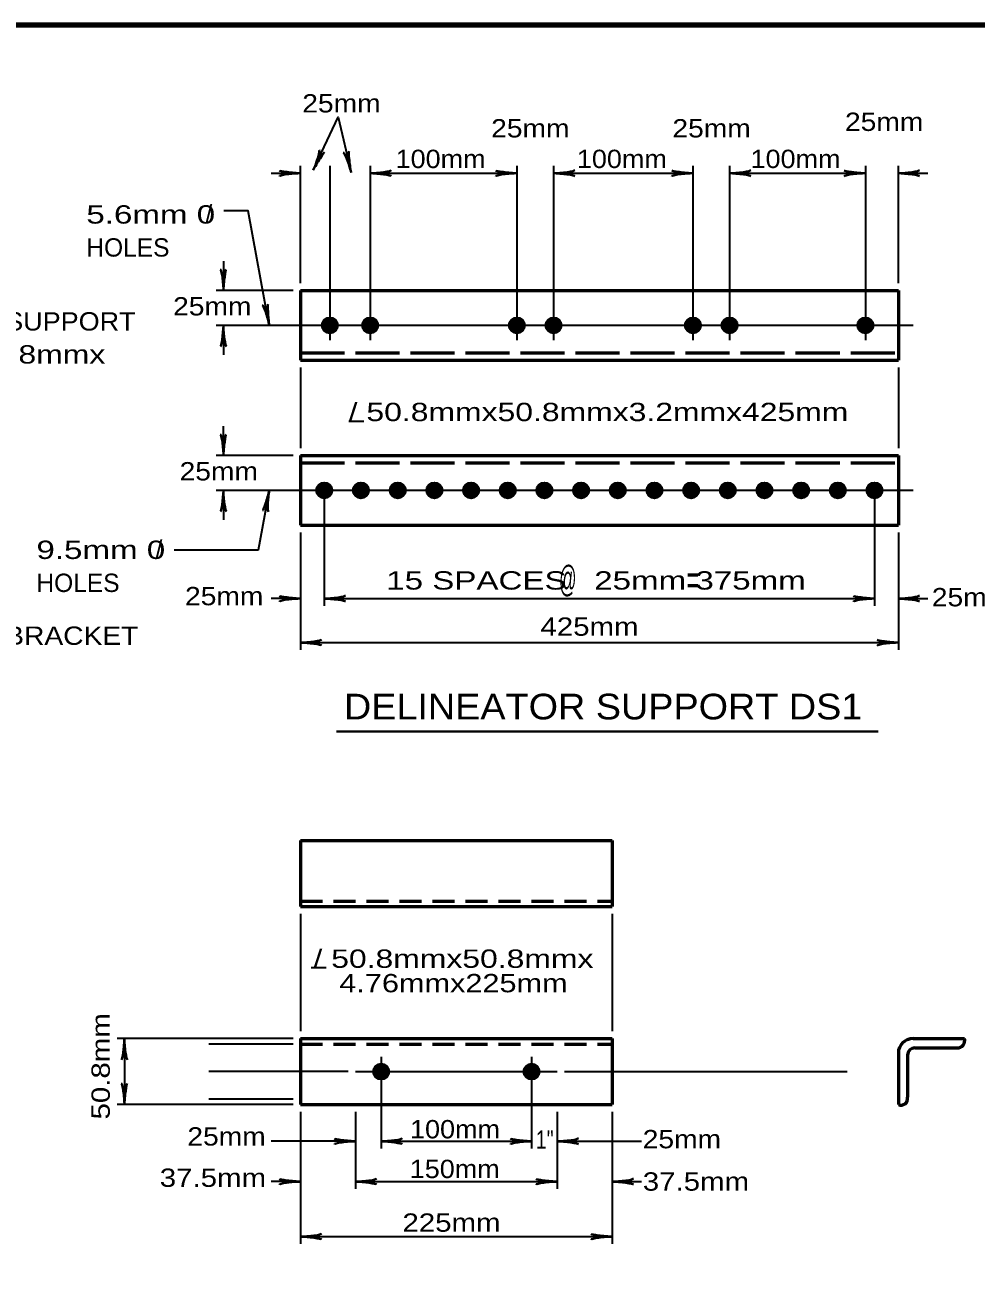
# Model space of a CAD drawing. Extents: x -105 to 751, y -65 to 479.
# Drawn here: x 441.4 to 597, y 268.5 to 472.7 of the extents above; entities that cross this region are included whole.
import ezdxf
from ezdxf.enums import TextEntityAlignment as Align

# ---------------------------------------------------------------- set-up
doc = ezdxf.new("R2010")
doc.units = 0
doc.header["$LTSCALE"] = 1.2
doc.linetypes.add('LONG_DASHED', pattern=[7.5, 6, -1.5])
doc.linetypes.add('MEDIUM_DASHED', pattern=[4.5, 3, -1.5])
doc.layers.add('1', color=7, linetype='Continuous', lineweight=35)

msp = doc.modelspace()

# ---------------------------------------------------------------- hatches: boundary and pattern name
at = {"layer": '1'}
for points in [[(492.465, 423.538, 1), (490.065, 423.538, 1)], [(499.065, 423.538, 1), (496.665, 423.538, 1)], [(523.065, 423.538, 1), (520.665, 423.538, 1)], [(529.065, 423.538, 1), (526.665, 423.538, 1)], [(551.865, 423.538, 1), (549.465, 423.538, 1)], [(557.865, 423.538, 1), (555.465, 423.538, 1)], [(580.065, 423.538, 1), (577.665, 423.538, 1)], [(491.565, 396.538, 1), (489.165, 396.538, 1)], [(497.565, 396.538, 1), (495.165, 396.538, 1)], [(503.565, 396.538, 1), (501.165, 396.538, 1)], [(509.565, 396.538, 1), (507.165, 396.538, 1)], [(515.565, 396.538, 1), (513.165, 396.538, 1)], [(521.565, 396.538, 1), (519.165, 396.538, 1)], [(527.565, 396.538, 1), (525.165, 396.538, 1)], [(533.565, 396.538, 1), (531.165, 396.538, 1)], [(539.565, 396.538, 1), (537.165, 396.538, 1)], [(545.565, 396.538, 1), (543.165, 396.538, 1)], [(551.565, 396.538, 1), (549.165, 396.538, 1)], [(557.565, 396.538, 1), (555.165, 396.538, 1)], [(563.565, 396.538, 1), (561.165, 396.538, 1)], [(569.565, 396.538, 1), (567.165, 396.538, 1)], [(575.565, 396.538, 1), (573.165, 396.538, 1)], [(581.565, 396.538, 1), (579.165, 396.538, 1)], [(500.865, 301.438, 1), (498.465, 301.438, 1)], [(525.465, 301.438, 1), (523.065, 301.438, 1)]]:
    msp.add_hatch(color=256, dxfattribs=at).paths.add_polyline_path(points)

# ---------------------------------------------------------------- linework, layer by layer
for p, q in [((486.465, 430.438), (486.465, 449.638)), ((491.265, 449.638), (491.265, 421.138)), ((497.865, 449.638), (497.865, 421.138)), ((521.865, 449.638), (521.865, 421.138)), ((527.865, 449.638), (527.865, 421.138)), ((550.665, 449.638), (550.665, 421.138)), ((556.665, 449.638), (556.665, 421.138)), ((578.865, 449.638), (578.865, 421.138)), ((584.265, 430.438), (584.265, 449.638)), ((481.665, 448.438), (486.465, 448.438)), ((497.865, 448.438), (521.865, 448.438)), ((527.865, 448.438), (550.665, 448.438)), ((556.665, 448.438), (578.865, 448.438)), ((584.265, 448.438), (589.065, 448.438)), ((473.865, 434.038), (473.865, 429.238)), ((485.265, 429.238), (472.665, 429.238)), ((586.665, 423.538), (472.665, 423.538)), ((473.865, 423.538), (473.865, 418.738)), ((486.465, 416.638), (486.465, 403.438)), ((584.265, 416.638), (584.265, 403.438)), ((473.865, 402.238), (473.865, 407.038)), ((494.355, 407.872), (496.841, 407.872)), ((485.265, 402.238), (472.665, 402.238)), ((586.665, 396.538), (472.665, 396.538)), ((473.865, 396.538), (473.865, 391.738)), ((490.365, 396.538), (490.365, 377.638)), ((580.365, 396.538), (580.365, 377.638)), ((486.465, 389.638), (486.465, 370.438)), ((584.265, 389.638), (584.265, 370.438)), ((486.465, 378.838), (481.665, 378.838)), ((490.365, 378.838), (580.365, 378.838)), ((584.265, 378.838), (589.065, 378.838)), ((486.465, 371.638), (584.265, 371.638)), ((486.465, 327.238), (486.465, 308.038)), ((537.465, 327.238), (537.465, 308.038)), ((488.207, 318.451), (490.693, 318.451)), ((485.265, 306.838), (456.465, 306.838)), ((457.665, 306.838), (457.665, 296.038)), ((485.265, 305.938), (471.465, 305.938)), ((499.665, 303.838), (499.665, 288.838)), ((524.265, 303.838), (524.265, 288.838)), ((494.265, 301.438), (471.465, 301.438)), ((495.465, 301.438), (528.465, 301.438)), ((529.665, 301.438), (575.865, 301.438)), ((485.265, 296.938), (471.465, 296.938)), ((485.265, 296.038), (456.465, 296.038)), ((486.465, 294.838), (486.465, 273.238)), ((495.465, 294.838), (495.465, 282.238)), ((528.465, 294.838), (528.465, 282.238)), ((537.465, 294.838), (537.465, 273.238)), ((495.465, 290.038), (481.665, 290.038)), ((499.665, 290.038), (524.265, 290.038)), ((528.465, 290.038), (542.265, 290.038)), ((486.465, 283.438), (481.665, 283.438)), ((495.465, 283.438), (528.465, 283.438)), ((537.465, 283.438), (542.265, 283.438)), ((486.465, 274.438), (537.465, 274.438))]:
    msp.add_line(p, q, dxfattribs=at)
at = {"layer": '1', "lineweight": 53}
for p, q in [((486.465, 429.238), (584.265, 429.238)), ((486.465, 429.238), (486.465, 417.838)), ((584.265, 429.238), (584.265, 417.838)), ((486.465, 417.838), (584.265, 417.838)), ((486.465, 402.238), (584.265, 402.238)), ((486.465, 402.238), (486.465, 390.838)), ((584.265, 402.238), (584.265, 390.838)), ((486.465, 390.838), (584.265, 390.838)), ((486.465, 339.238), (537.465, 339.238)), ((486.465, 339.238), (486.465, 328.438)), ((537.465, 339.238), (537.465, 328.438)), ((486.465, 328.438), (537.465, 328.438)), ((486.465, 306.838), (537.465, 306.838)), ((486.465, 306.838), (486.465, 296.038)), ((537.465, 306.838), (537.465, 296.038)), ((586.665, 306.838), (595.065, 306.838)), ((584.265, 304.438), (584.265, 296.038)), ((586.965, 305.338), (593.865, 305.338)), ((585.765, 304.138), (585.765, 297.238)), ((486.465, 296.038), (537.465, 296.038))]:
    msp.add_line(p, q, dxfattribs=at)
at = {"layer": '1', "linetype": 'LONG_DASHED', "lineweight": 53}
for p, q in [((486.465, 419.038), (584.265, 419.038)), ((486.465, 401.038), (584.265, 401.038))]:
    msp.add_line(p, q, dxfattribs=at)
at = {"layer": '1', "lineweight": 40}
msp.add_line((492.332, 357.076), (580.978, 357.076), dxfattribs=at)
at = {"layer": '1', "linetype": 'MEDIUM_DASHED', "lineweight": 53}
for p, q in [((486.465, 329.338), (537.465, 329.338)), ((486.465, 305.938), (537.465, 305.938))]:
    msp.add_line(p, q, dxfattribs=at)
at = {"layer": '1', "lineweight": 158}
msp.add_lwpolyline([(744.128, 472.7), (-47.572, 472.6), (-47.472, -53.4)], dxfattribs=at)
at = {"layer": '1'}
for points in [[(488.534, 448.93), (492.618, 457.633), (494.748, 448.575)], [(481.361, 423.538), (477.884, 442.274), (473.948, 442.274)], [(481.361, 396.538), (479.544, 386.747), (465.806, 386.747)]]:
    msp.add_lwpolyline(points, dxfattribs=at)
at = {"layer": '1', "lineweight": 53}
for centre in [(491.265, 423.538), (497.865, 423.538), (521.865, 423.538), (527.865, 423.538), (550.665, 423.538), (556.665, 423.538), (578.865, 423.538), (490.365, 396.538), (496.365, 396.538), (502.365, 396.538), (508.365, 396.538), (514.365, 396.538), (520.365, 396.538), (526.365, 396.538), (532.365, 396.538), (538.365, 396.538), (544.365, 396.538), (550.365, 396.538), (556.365, 396.538), (562.365, 396.538), (568.365, 396.538), (574.365, 396.538), (580.365, 396.538), (499.665, 301.438), (524.265, 301.438)]:
    msp.add_circle(centre, 1.2, dxfattribs=at)
for centre, radius, start, end in [((586.665, 304.438), 2.4, 90, 180), ((593.953, 306.498), 1.163, 265.65667, 17.02372), ((586.965, 304.138), 1.2, 90, 180), ((584.699, 297.033), 1.086, 246.44767, 10.87194)]:
    msp.add_arc(centre, radius, start, end, dxfattribs=at)
at = {"layer": '1', "lineweight": 40}
for centre, major_axis, ratio, start_param, end_param in [((488.79, 450.257), (-0.741, -2.019), 0.122415, 0.8963533, 3.1415927), ((489.335, 450.04), (-1.086, -1.819), 0.07063, 3.1407148, 5.41811), ((494.126, 449.774), (0.673, -2.043), 0.122415, 0.8963533, 3.1415927), ((494.688, 449.942), (0.277, -2.1), 0.07063, 3.1407148, 5.41811), ((485.156, 448.107), (2.143, 0.187), 0.122415, 0.8963533, 3.1415927), ((485.156, 448.107), (2.143, 0.187), 0.122415, 0.8963533, 3.1415927), ((485.121, 448.692), (2.108, -0.211), 0.07063, 3.1407148, 5.41811), ((485.121, 448.692), (2.108, -0.211), 0.07063, 3.1407148, 5.41811), ((499.21, 448.184), (-2.108, 0.211), 0.07063, 3.1407148, 5.41811), ((499.21, 448.184), (-2.108, 0.211), 0.07063, 3.1407148, 5.41811), ((499.175, 448.77), (-2.143, -0.187), 0.122415, 0.8963533, 3.1415927), ((499.175, 448.77), (-2.143, -0.187), 0.122415, 0.8963533, 3.1415927), ((520.556, 448.107), (2.143, 0.187), 0.122415, 0.8963533, 3.1415927), ((520.556, 448.107), (2.143, 0.187), 0.122415, 0.8963533, 3.1415927), ((520.521, 448.692), (2.108, -0.211), 0.07063, 3.1407148, 5.41811), ((520.521, 448.692), (2.108, -0.211), 0.07063, 3.1407148, 5.41811), ((529.21, 448.184), (-2.108, 0.211), 0.07063, 3.1407148, 5.41811), ((529.21, 448.184), (-2.108, 0.211), 0.07063, 3.1407148, 5.41811), ((529.175, 448.77), (-2.143, -0.187), 0.122415, 0.8963533, 3.1415927), ((529.175, 448.77), (-2.143, -0.187), 0.122415, 0.8963533, 3.1415927), ((549.356, 448.107), (2.143, 0.187), 0.122415, 0.8963533, 3.1415927), ((549.356, 448.107), (2.143, 0.187), 0.122415, 0.8963533, 3.1415927), ((549.321, 448.692), (2.108, -0.211), 0.07063, 3.1407148, 5.41811), ((549.321, 448.692), (2.108, -0.211), 0.07063, 3.1407148, 5.41811), ((558.01, 448.184), (-2.108, 0.211), 0.07063, 3.1407148, 5.41811), ((558.01, 448.184), (-2.108, 0.211), 0.07063, 3.1407148, 5.41811), ((557.975, 448.77), (-2.143, -0.187), 0.122415, 0.8963533, 3.1415927), ((557.975, 448.77), (-2.143, -0.187), 0.122415, 0.8963533, 3.1415927), ((577.556, 448.107), (2.143, 0.187), 0.122415, 0.8963533, 3.1415927), ((577.556, 448.107), (2.143, 0.187), 0.122415, 0.8963533, 3.1415927), ((577.521, 448.692), (2.108, -0.211), 0.07063, 3.1407148, 5.41811), ((577.521, 448.692), (2.108, -0.211), 0.07063, 3.1407148, 5.41811), ((585.61, 448.184), (-2.108, 0.211), 0.07063, 3.1407148, 5.41811), ((585.61, 448.184), (-2.108, 0.211), 0.07063, 3.1407148, 5.41811), ((585.575, 448.77), (-2.143, -0.187), 0.122415, 0.8963533, 3.1415927), ((585.575, 448.77), (-2.143, -0.187), 0.122415, 0.8963533, 3.1415927), ((473.534, 430.548), (0.187, -2.143), 0.122415, 0.8963533, 3.1415927), ((473.534, 430.548), (0.187, -2.143), 0.122415, 0.8963533, 3.1415927), ((474.119, 430.583), (-0.211, -2.108), 0.07063, 3.1407148, 5.41811), ((474.119, 430.583), (-0.211, -2.108), 0.07063, 3.1407148, 5.41811), ((480.796, 424.765), (0.575, -2.073), 0.122415, 0.8963533, 3.1415927), ((480.796, 424.765), (0.575, -2.073), 0.122415, 0.8963533, 3.1415927), ((481.365, 424.907), (0.177, -2.111), 0.07063, 3.1407148, 5.41811), ((481.365, 424.907), (0.177, -2.111), 0.07063, 3.1407148, 5.41811), ((473.611, 422.194), (0.211, 2.108), 0.07063, 3.1407148, 5.41811), ((473.611, 422.194), (0.211, 2.108), 0.07063, 3.1407148, 5.41811), ((474.197, 422.229), (-0.187, 2.143), 0.122415, 0.8963533, 3.1415927), ((474.197, 422.229), (-0.187, 2.143), 0.122415, 0.8963533, 3.1415927), ((473.534, 403.548), (0.187, -2.143), 0.122415, 0.8963533, 3.1415927), ((473.534, 403.548), (0.187, -2.143), 0.122415, 0.8963533, 3.1415927), ((474.119, 403.583), (-0.211, -2.108), 0.07063, 3.1407148, 5.41811), ((474.119, 403.583), (-0.211, -2.108), 0.07063, 3.1407148, 5.41811), ((473.611, 395.194), (0.211, 2.108), 0.07063, 3.1407148, 5.41811), ((473.611, 395.194), (0.211, 2.108), 0.07063, 3.1407148, 5.41811), ((474.197, 395.229), (-0.187, 2.143), 0.122415, 0.8963533, 3.1415927), ((474.197, 395.229), (-0.187, 2.143), 0.122415, 0.8963533, 3.1415927), ((480.866, 395.262), (-0.592, -2.034), 0.07063, 6.2823074, 8.5597026), ((480.866, 395.262), (-0.592, -2.034), 0.07063, 6.2823074, 8.5597026), ((481.448, 395.19), (0.207, 2.141), 0.122415, 0.8963533, 3.1415927), ((481.448, 395.19), (0.207, 2.141), 0.122415, 0.8963533, 3.1415927), ((485.156, 378.507), (2.143, 0.187), 0.122415, 0.8963533, 3.1415927), ((485.156, 378.507), (2.143, 0.187), 0.122415, 0.8963533, 3.1415927), ((485.121, 379.092), (2.108, -0.211), 0.07063, 3.1407148, 5.41811), ((485.121, 379.092), (2.108, -0.211), 0.07063, 3.1407148, 5.41811), ((491.71, 378.584), (-2.108, 0.211), 0.07063, 3.1407148, 5.41811), ((491.71, 378.584), (-2.108, 0.211), 0.07063, 3.1407148, 5.41811), ((491.675, 379.17), (-2.143, -0.187), 0.122415, 0.8963533, 3.1415927), ((491.675, 379.17), (-2.143, -0.187), 0.122415, 0.8963533, 3.1415927), ((579.056, 378.507), (2.143, 0.187), 0.122415, 0.8963533, 3.1415927), ((579.056, 378.507), (2.143, 0.187), 0.122415, 0.8963533, 3.1415927), ((579.056, 378.507), (2.143, 0.187), 0.122415, 0.8963533, 3.1415927), ((579.021, 379.092), (2.108, -0.211), 0.07063, 3.1407148, 5.41811), ((579.021, 379.092), (2.108, -0.211), 0.07063, 3.1407148, 5.41811), ((579.021, 379.092), (2.108, -0.211), 0.07063, 3.1407148, 5.41811), ((585.61, 378.584), (-2.108, 0.211), 0.07063, 3.1407148, 5.41811), ((585.575, 379.17), (-2.143, -0.187), 0.122415, 0.8963533, 3.1415927), ((487.775, 371.97), (-2.143, -0.187), 0.122415, 0.8963533, 3.1415927), ((487.775, 371.97), (-2.143, -0.187), 0.122415, 0.8963533, 3.1415927), ((582.921, 371.892), (2.108, -0.211), 0.07063, 3.1407148, 5.41811), ((582.921, 371.892), (2.108, -0.211), 0.07063, 3.1407148, 5.41811), ((487.81, 371.384), (-2.108, 0.211), 0.07063, 3.1407148, 5.41811), ((487.81, 371.384), (-2.108, 0.211), 0.07063, 3.1407148, 5.41811), ((582.956, 371.307), (2.143, 0.187), 0.122415, 0.8963533, 3.1415927), ((582.956, 371.307), (2.143, 0.187), 0.122415, 0.8963533, 3.1415927), ((457.411, 305.494), (0.211, 2.108), 0.07063, 3.1407148, 5.41811), ((457.411, 305.494), (0.211, 2.108), 0.07063, 3.1407148, 5.41811), ((457.997, 305.529), (-0.187, 2.143), 0.122415, 0.8963533, 3.1415927), ((457.997, 305.529), (-0.187, 2.143), 0.122415, 0.8963533, 3.1415927), ((457.334, 297.348), (0.187, -2.143), 0.122415, 0.8963533, 3.1415927), ((457.334, 297.348), (0.187, -2.143), 0.122415, 0.8963533, 3.1415927), ((457.919, 297.383), (-0.211, -2.108), 0.07063, 3.1407148, 5.41811), ((457.919, 297.383), (-0.211, -2.108), 0.07063, 3.1407148, 5.41811), ((494.156, 289.707), (2.143, 0.187), 0.122415, 0.8963533, 3.1415927), ((494.156, 289.707), (2.143, 0.187), 0.122415, 0.8963533, 3.1415927), ((494.121, 290.292), (2.108, -0.211), 0.07063, 3.1407148, 5.41811), ((494.121, 290.292), (2.108, -0.211), 0.07063, 3.1407148, 5.41811), ((501.01, 289.784), (-2.108, 0.211), 0.07063, 3.1407148, 5.41811), ((501.01, 289.784), (-2.108, 0.211), 0.07063, 3.1407148, 5.41811), ((500.975, 290.37), (-2.143, -0.187), 0.122415, 0.8963533, 3.1415927), ((500.975, 290.37), (-2.143, -0.187), 0.122415, 0.8963533, 3.1415927), ((522.956, 289.707), (2.143, 0.187), 0.122415, 0.8963533, 3.1415927), ((522.956, 289.707), (2.143, 0.187), 0.122415, 0.8963533, 3.1415927), ((522.921, 290.292), (2.108, -0.211), 0.07063, 3.1407148, 5.41811), ((522.921, 290.292), (2.108, -0.211), 0.07063, 3.1407148, 5.41811), ((529.81, 289.784), (-2.108, 0.211), 0.07063, 3.1407148, 5.41811), ((529.81, 289.784), (-2.108, 0.211), 0.07063, 3.1407148, 5.41811), ((529.775, 290.37), (-2.143, -0.187), 0.122415, 0.8963533, 3.1415927), ((529.775, 290.37), (-2.143, -0.187), 0.122415, 0.8963533, 3.1415927), ((485.121, 283.692), (2.108, -0.211), 0.07063, 3.1407148, 5.41811), ((485.121, 283.692), (2.108, -0.211), 0.07063, 3.1407148, 5.41811), ((496.775, 283.77), (-2.143, -0.187), 0.122415, 0.8963533, 3.1415927), ((496.775, 283.77), (-2.143, -0.187), 0.122415, 0.8963533, 3.1415927), ((527.121, 283.692), (2.108, -0.211), 0.07063, 3.1407148, 5.41811), ((527.121, 283.692), (2.108, -0.211), 0.07063, 3.1407148, 5.41811), ((538.775, 283.77), (-2.143, -0.187), 0.122415, 0.8963533, 3.1415927), ((538.775, 283.77), (-2.143, -0.187), 0.122415, 0.8963533, 3.1415927), ((485.156, 283.107), (2.143, 0.187), 0.122415, 0.8963533, 3.1415927), ((485.156, 283.107), (2.143, 0.187), 0.122415, 0.8963533, 3.1415927), ((496.81, 283.184), (-2.108, 0.211), 0.07063, 3.1407148, 5.41811), ((496.81, 283.184), (-2.108, 0.211), 0.07063, 3.1407148, 5.41811), ((527.156, 283.107), (2.143, 0.187), 0.122415, 0.8963533, 3.1415927), ((527.156, 283.107), (2.143, 0.187), 0.122415, 0.8963533, 3.1415927), ((538.81, 283.184), (-2.108, 0.211), 0.07063, 3.1407148, 5.41811), ((538.81, 283.184), (-2.108, 0.211), 0.07063, 3.1407148, 5.41811), ((487.81, 274.184), (-2.108, 0.211), 0.07063, 3.1407148, 5.41811), ((487.81, 274.184), (-2.108, 0.211), 0.07063, 3.1407148, 5.41811), ((487.775, 274.77), (-2.143, -0.187), 0.122415, 0.8963533, 3.1415927), ((487.775, 274.77), (-2.143, -0.187), 0.122415, 0.8963533, 3.1415927), ((536.156, 274.107), (2.143, 0.187), 0.122415, 0.8963533, 3.1415927), ((536.121, 274.692), (2.108, -0.211), 0.07063, 3.1407148, 5.41811)]:
    msp.add_ellipse(centre, major_axis=major_axis, ratio=ratio, start_param=start_param, end_param=end_param, dxfattribs=at)

# ---------------------------------------------------------------- texts
at = {"layer": '1'}
for s, height, width, p in [('25mm', 3, 1.15, (486.757, 458.377)), ('25mm', 3, 1.15, (575.535, 455.358)), ('25mm', 3, 1.15, (517.652, 454.293)), ('25mm', 3, 1.15, (547.303, 454.293)), ('100mm', 3, 1.1, (502.028, 449.286)), ('100mm', 3, 1.1, (531.68, 449.286)), ('100mm', 3, 1.1, (560.089, 449.286)), ('5.6mm 0', 3, 1.35, (451.439, 440.198)), ('25mm', 3, 1.15, (465.628, 425.166)), ('DELINEATOR SUPPORT', 3, 1.1, (408.739, 422.699)), ('/ 50.8mmx50.8mmx', 3, 1.3, (408.739, 417.299)), ('/ 50.8mmx50.8mmx3.2mmx425mm', 3, 1.3, (494.355, 407.872)), ('25mm', 3, 1.15, (466.693, 398.171)), ('9.5mm 0', 3, 1.35, (443.272, 385.32)), ('@', 4.2, 0.5, (528.764, 380.004)), ('15 SPACES   25mm 375mm', 3, 1.35, (500.495, 380.311)), ('=', 4.8, 0.55, (549.624, 379.532)), ('25mm', 3, 1.15, (467.581, 377.747)), ('25mm', 3, 1.15, (589.739, 377.57)), ('425mm', 3, 1.2, (525.717, 372.753)), ('STAINLESS STEEL BRACKET', 3, 1.15, (395.605, 371.27)), ('DELINEATOR SUPPORT DS1', 4.2, 1.1, (493.579, 359.072)), ('25mm', 3, 1.15, (467.964, 289.335)), ('100mm', 3, 1.1, (504.387, 290.516)), ('1"', 3, 0.8, (524.957, 288.813)), ('25mm', 3, 1.15, (542.449, 288.891)), ('150mm', 3, 1.1, (504.342, 284.015)), ('37.5mm', 3, 1.2, (463.448, 282.579)), ('37.5mm', 3, 1.2, (542.461, 281.957)), ('225mm', 3, 1.2, (503.143, 275.235))]:
    msp.add_text(s, height=height, dxfattribs=dict(at, width=width)).set_placement(p)
for s, p in [('/', (470.918, 440.245)), ('HOLES', (451.439, 434.798)), ('/', (462.751, 385.366)), ('HOLES', (443.272, 379.92))]:
    msp.add_text(s, height=3, dxfattribs=at).set_placement(p)
for s, width, p in [('/ 50.8mmx50.8mmx', 1.3, (511.489, 318.418)), ('4.76mmx225mm', 1.25, (511.489, 314.418))]:
    msp.add_text(s, height=3, dxfattribs=dict(at, width=width)).set_placement(p, align=Align.CENTER)
at = {"layer": '1', "width": 1.2}
msp.add_text('50.8mm', height=3, rotation=90, dxfattribs=at).set_placement((455.279, 293.607))

doc.saveas('drawing.dxf')
